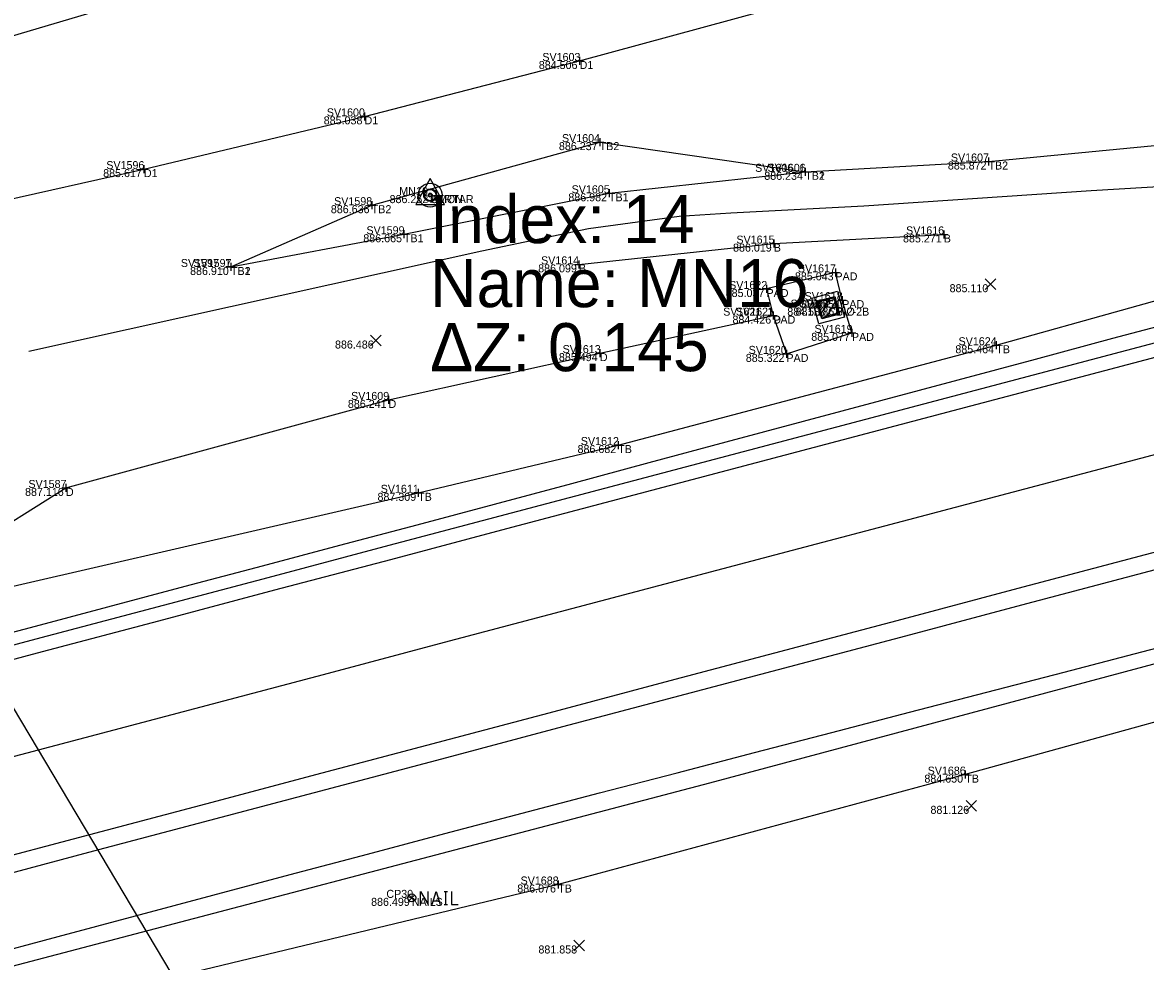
# Model space of a CAD drawing. Extents: x 2125299 to 2129212, y 713100 to 714300.
# Drawn here: x 2127665 to 2127805.3, y 713771.1 to 713888.4 of the extents above; entities that cross this region are included whole.
import ezdxf

# ---------------------------------------------------------------- set-up
doc = ezdxf.new("R2010")
doc.units = 0
for name, color, linetype in [('_CIVIL_CONSTRUCTION', 7, 'Continuous'), ('DR_X_Ditch', 7, 'Continuous'), ('DR_X_Storm_Sewer', 7, 'Continuous'), ('PV_X_EOP', 7, 'Continuous'), ('PV_X_Shoulder_Rumble_Strip', 7, 'Continuous'), ('RD_X_Concrete_Pad', 7, 'Continuous'), ('RS_Raster1', 7, 'Continuous'), ('RW_P_Esmt_TMP', 7, 'Continuous'), ('RW_X_CL', 7, 'Continuous'), ('RW_X_CL_100_Bearings', 7, 'Continuous'), ('RW_X_CL_100_Cardinal_Points', 7, 'Continuous'), ('RW_X_Esmt_CH', 7, 'Continuous'), ('RW_X_Fee_WL', 7, 'Continuous'), ('SC_Scratch1', 7, 'Continuous'), ('SC_Scratch2', 7, 'Continuous'), ('SV_P_Aerial_Targets', 7, 'Continuous'), ('SV_X_Break_Lines', 7, 'Continuous'), ('SV_X_Mon_Cells_Found', 7, 'Continuous'), ('SV_X_Text_Comment', 7, 'Continuous'), ('SV_X_Text_Elevation', 7, 'Continuous'), ('SV_X_Text_Name', 7, 'Continuous'), ('SV_X_Top_of_Bank', 7, 'Continuous')]:
    doc.layers.add(name, color=color, linetype=linetype)

msp = doc.modelspace()

# ---------------------------------------------------------------- linework, layer by layer
at = {"layer": '_CIVIL_CONSTRUCTION'}
msp.add_line((2127715.95, 713866.84), (2127715.95, 713866.84), dxfattribs=at)
msp.add_lwpolyline([(2127659.73, 713795.61), (2127674.23, 713799.44), (2127688.74, 713803.28), (2127703.24, 713807.12), (2127717.74, 713810.96), (2127732.24, 713814.8), (2127746.74, 713818.64), (2127761.24, 713822.47), (2127775.74, 713826.31), (2127790.24, 713830.15), (2127804.74, 713833.98), (2127819.24, 713837.82), (2127833.74, 713841.66), (2127848.24, 713845.49), (2127862.75, 713849.33), (2127877.25, 713853.16), (2127891.75, 713857), (2127906.25, 713860.83), (2127920.75, 713864.67)], dxfattribs=at)
msp.add_circle((2127715.95, 713866.84), 0.25, dxfattribs=at)
at = {"layer": 'DR_X_Ditch'}
for points in [[(2127104.46, 713722.2), (2127161.17, 713739.36), (2127224.94, 713755.07), (2127279.95, 713770.84), (2127341.71, 713787.57), (2127396.23, 713800.84), (2127459.54, 713814.71), (2127515.88, 713829.56), (2127633.42, 713858.63), (2127660.82, 713865.77), (2127680.17, 713870.09), (2127707.74, 713876.68), (2127734.62, 713883.6), (2127780.13, 713896.01), (2127811.25, 713900.24), (2127854.87, 713906.28), (2127890.1, 713912.55), (2127900.96, 713914.65)], [(2127114.72, 713683.53), (2127174.42, 713700.51), (2127233.48, 713715.29), (2127290.34, 713734.33), (2127349.42, 713751.95), (2127405.14, 713769), (2127465.12, 713782.63), (2127526.43, 713796.66), (2127583.18, 713810.08), (2127641.36, 713825.21), (2127649.66, 713823.32), (2127658.57, 713822.87), (2127670.43, 713830.25), (2127710.74, 713841.25), (2127737.15, 713847.1), (2127758.82, 713851.78)]]:
    msp.add_lwpolyline(points, dxfattribs=at)
at = {"layer": 'DR_X_Storm_Sewer'}
msp.add_line((2127551.46, 713991.15), (2127754.53, 713650.69), dxfattribs=at)
at = {"layer": 'PV_X_EOP'}
for points in [[(2127656.31, 713810.27), (2127665.98, 713812.83), (2127675.65, 713815.39), (2127685.31, 713817.96), (2127694.98, 713820.52), (2127704.64, 713823.08), (2127714.31, 713825.65), (2127723.97, 713828.22), (2127733.63, 713830.82), (2127743.29, 713833.42), (2127752.94, 713836.01), (2127762.6, 713838.6), (2127772.26, 713841.19), (2127781.92, 713843.77), (2127791.58, 713846.36), (2127801.24, 713848.95), (2127810.91, 713851.5)], [(2127659.79, 713771.64), (2127669.45, 713774.21), (2127679.11, 713776.79), (2127688.78, 713779.36), (2127698.44, 713781.93), (2127708.1, 713784.51), (2127717.77, 713787.08), (2127727.44, 713789.63), (2127737.11, 713792.15), (2127746.79, 713794.66), (2127756.47, 713797.18), (2127766.15, 713799.7), (2127775.83, 713802.22), (2127785.5, 713804.73), (2127795.18, 713807.25), (2127804.86, 713809.77), (2127814.54, 713812.29)]]:
    msp.add_lwpolyline(points, dxfattribs=at)
at = {"layer": 'PV_X_Shoulder_Rumble_Strip'}
for points in [[(2127652.21, 713807.54), (2127666.7, 713811.39), (2127681.2, 713815.24), (2127695.69, 713819.08), (2127710.19, 713822.92), (2127724.69, 713826.75), (2127739.19, 713830.59), (2127753.68, 713834.42), (2127768.18, 713838.25), (2127782.68, 713842.09), (2127797.18, 713845.92), (2127811.68, 713849.75), (2127826.18, 713853.59), (2127840.68, 713857.42), (2127855.17, 713861.25), (2127869.67, 713865.09), (2127884.17, 713868.92), (2127898.67, 713872.75), (2127913.17, 713876.59), (2127927.67, 713880.42), (2127936.81, 713882.83)], [(2127659.41, 713781.04), (2127673.9, 713784.89), (2127688.4, 713788.73), (2127702.89, 713792.57), (2127717.39, 713796.42), (2127731.89, 713800.26), (2127746.38, 713804.1), (2127760.88, 713807.95), (2127775.37, 713811.79), (2127789.87, 713815.63), (2127804.37, 713819.48), (2127818.86, 713823.32), (2127833.36, 713827.16), (2127847.85, 713831.01), (2127862.35, 713834.85), (2127876.84, 713838.69), (2127891.34, 713842.54), (2127905.84, 713846.37), (2127920.34, 713850.2), (2127928.07, 713852.23)]]:
    msp.add_lwpolyline(points, dxfattribs=at)
at = {"layer": 'RD_X_Concrete_Pad'}
msp.add_lwpolyline([(2127757.97, 713855.11), (2127758.82, 713851.78), (2127760.46, 713847), (2127768.65, 713849.63), (2127767.43, 713853.72), (2127766.58, 713857.19)], close=True, dxfattribs=at)
at = {"layer": 'RS_Raster1'}
msp.add_lwpolyline([(2127665.8, 713847.33), (2127722.38, 713859.86), (2127735.74, 713862.67), (2127747.07, 713864.19), (2127753.51, 713864.63), (2127770.12, 713865.48), (2127798.56, 713867.4), (2127815.33, 713868.4), (2127824.46, 713869.11), (2127836.01, 713870.37), (2127852.68, 713872.56), (2127871.22, 713875.21), (2127888.51, 713877.86), (2127910.9, 713881.86), (2127918.62, 713883.3), (2127925.53, 713884.74), (2127939.36, 713888.03)], dxfattribs=at)
at = {"layer": 'RW_X_CL'}
for radius in [1.5, 0.8]:
    msp.add_circle((2127715.95, 713866.84), radius, dxfattribs=at)
at = {"layer": 'RW_X_CL_100_Bearings'}
for p, q in [((2127765.24, 713854.39), (2127765.24, 713854.39)), ((2127765.42, 713853.75), (2127765.42, 713853.75)), ((2127764.71, 713852.52), (2127764.71, 713852.52)), ((2127765.68, 713852.78), (2127765.68, 713852.78)), ((2127765.68, 713852.78), (2127765.68, 713852.78)), ((2127765.68, 713852.78), (2127765.68, 713852.78)), ((2127766.64, 713853.04), (2127766.64, 713853.04)), ((2127765.94, 713851.82), (2127765.94, 713851.82)), ((2127766.11, 713851.17), (2127766.11, 713851.17))]:
    msp.add_line(p, q, dxfattribs=at)
at = {"layer": 'RW_X_CL_100_Cardinal_Points'}
for p, q in [((2127766.2, 713852.79), (2127767.2, 713852.79)), ((2127766.7, 713853.29), (2127766.7, 713852.29)), ((2127766.7, 713852.79), (2127766.7, 713852.79))]:
    msp.add_line(p, q, dxfattribs=at)
at = {"layer": 'SC_Scratch1'}
msp.add_lwpolyline([(2127133.38, 713627.43), (2127166.26, 713637.18), (2127280.77, 713668.85), (2127395.3, 713699.47), (2127509.42, 713729.99), (2127750.89, 713793.4), (2127929.41, 713841.22)], dxfattribs=at)
at = {"layer": 'SC_Scratch2'}
for points in [[(2127653.02, 713805.95), (2127667.52, 713809.8), (2127682.02, 713813.65), (2127696.52, 713817.5), (2127711.02, 713821.33), (2127725.52, 713825.17), (2127740.02, 713829), (2127754.52, 713832.83), (2127769.02, 713836.67), (2127783.52, 713840.5), (2127798.03, 713844.34), (2127812.53, 713848.17), (2127827.03, 713852.01), (2127841.53, 713855.84), (2127856.03, 713859.67), (2127870.54, 713863.51), (2127885.04, 713867.34), (2127899.54, 713871.18), (2127914.04, 713875.01), (2127928.54, 713878.84), (2127943.04, 713882.68), (2127957.55, 713886.51), (2127972.05, 713890.34)], [(2127658.93, 713783.11), (2127673.43, 713786.96), (2127687.93, 713790.8), (2127702.43, 713794.64), (2127716.93, 713798.49), (2127731.43, 713802.33), (2127745.92, 713806.18), (2127760.42, 713810.02), (2127774.92, 713813.87), (2127789.42, 713817.71), (2127803.92, 713821.55), (2127818.42, 713825.4), (2127832.92, 713829.24), (2127847.42, 713833.09), (2127861.92, 713836.93), (2127876.42, 713840.78), (2127890.92, 713844.62), (2127905.42, 713848.46), (2127919.92, 713852.28)]]:
    msp.add_lwpolyline(points, dxfattribs=at)
at = {"layer": 'SV_P_Aerial_Targets'}
msp.add_line((2127715.95, 713866.84), (2127715.95, 713866.84), dxfattribs=at)
msp.add_lwpolyline([(2127714.15, 713865.68), (2127717.75, 713865.68), (2127715.95, 713868.9)], close=True, dxfattribs=at)
for radius in [0.7, 0.16]:
    msp.add_circle((2127715.95, 713866.84), radius, dxfattribs=at)
at = {"layer": 'SV_X_Break_Lines'}
msp.add_lwpolyline([(2127734.52, 713858.19), (2127758.88, 713860.78), (2127780.12, 713861.93)], dxfattribs=at)
at = {"layer": 'SV_X_Mon_Cells_Found'}
for p, q in [((2127734.12, 713883.6), (2127735.12, 713883.6)), ((2127734.62, 713884.1), (2127734.62, 713883.1)), ((2127734.62, 713883.6), (2127734.62, 713883.6)), ((2127707.24, 713876.68), (2127708.24, 713876.68)), ((2127707.74, 713877.18), (2127707.74, 713876.18)), ((2127707.74, 713876.68), (2127707.74, 713876.68)), ((2127736.63, 713873.46), (2127737.63, 713873.46)), ((2127737.13, 713873.96), (2127737.13, 713872.96)), ((2127737.13, 713873.46), (2127737.13, 713873.46)), ((2127680.17, 713870.59), (2127680.17, 713869.59)), ((2127785.21, 713871.04), (2127786.21, 713871.04)), ((2127785.71, 713871.54), (2127785.71, 713870.54)), ((2127785.71, 713871.04), (2127785.71, 713871.04)), ((2127679.67, 713870.09), (2127680.67, 713870.09)), ((2127680.17, 713870.09), (2127680.17, 713870.09)), ((2127762.31, 713869.75), (2127763.31, 713869.75)), ((2127762.31, 713869.75), (2127763.31, 713869.75)), ((2127762.81, 713870.25), (2127762.81, 713869.25)), ((2127762.81, 713870.25), (2127762.81, 713869.25)), ((2127762.81, 713869.75), (2127762.81, 713869.75)), ((2127762.81, 713869.75), (2127762.81, 713869.75)), ((2127737.79, 713867.07), (2127738.79, 713867.07)), ((2127738.29, 713867.57), (2127738.29, 713866.57)), ((2127738.29, 713867.07), (2127738.29, 713867.07)), ((2127708.14, 713865.58), (2127709.14, 713865.58)), ((2127708.64, 713866.08), (2127708.64, 713865.08)), ((2127708.64, 713865.58), (2127708.64, 713865.58)), ((2127712.66, 713862.45), (2127712.66, 713861.45)), ((2127780.12, 713862.43), (2127780.12, 713861.43)), ((2127712.16, 713861.95), (2127713.16, 713861.95)), ((2127712.66, 713861.95), (2127712.66, 713861.95)), ((2127758.38, 713860.78), (2127759.38, 713860.78)), ((2127758.88, 713861.28), (2127758.88, 713860.28)), ((2127758.88, 713860.78), (2127758.88, 713860.78)), ((2127779.62, 713861.93), (2127780.62, 713861.93)), ((2127780.12, 713861.93), (2127780.12, 713861.93)), ((2127691.05, 713858.36), (2127691.05, 713857.36)), ((2127691.05, 713858.36), (2127691.05, 713857.36)), ((2127734.02, 713858.19), (2127735.02, 713858.19)), ((2127734.52, 713858.69), (2127734.52, 713857.69)), ((2127734.52, 713858.19), (2127734.52, 713858.19)), ((2127690.55, 713857.86), (2127691.55, 713857.86)), ((2127690.55, 713857.86), (2127691.55, 713857.86)), ((2127691.05, 713857.86), (2127691.05, 713857.86)), ((2127691.05, 713857.86), (2127691.05, 713857.86)), ((2127766.08, 713857.19), (2127767.08, 713857.19)), ((2127766.58, 713857.69), (2127766.58, 713856.69)), ((2127766.58, 713857.19), (2127766.58, 713857.19)), ((2127757.97, 713855.61), (2127757.97, 713854.61)), ((2127757.47, 713855.11), (2127758.47, 713855.11)), ((2127757.97, 713855.11), (2127757.97, 713855.11)), ((2127767.43, 713854.22), (2127767.43, 713853.22)), ((2127766.93, 713853.72), (2127767.93, 713853.72)), ((2127767.43, 713853.72), (2127767.43, 713853.72)), ((2127758.32, 713851.78), (2127759.32, 713851.78)), ((2127758.32, 713851.78), (2127759.32, 713851.78)), ((2127758.82, 713852.28), (2127758.82, 713851.28)), ((2127758.82, 713852.28), (2127758.82, 713851.28)), ((2127758.82, 713851.78), (2127758.82, 713851.78)), ((2127758.82, 713851.78), (2127758.82, 713851.78)), ((2127768.15, 713849.63), (2127769.15, 713849.63)), ((2127768.65, 713850.13), (2127768.65, 713849.13)), ((2127768.65, 713849.63), (2127768.65, 713849.63)), ((2127786.69, 713848.58), (2127786.69, 713847.58)), ((2127736.65, 713847.1), (2127737.65, 713847.1)), ((2127737.15, 713847.6), (2127737.15, 713846.6)), ((2127737.15, 713847.1), (2127737.15, 713847.1)), ((2127759.96, 713847), (2127760.96, 713847)), ((2127760.46, 713847.5), (2127760.46, 713846.5)), ((2127760.46, 713847), (2127760.46, 713847)), ((2127786.19, 713848.08), (2127787.19, 713848.08)), ((2127786.69, 713848.08), (2127786.69, 713848.08)), ((2127710.24, 713841.25), (2127711.24, 713841.25)), ((2127710.74, 713841.75), (2127710.74, 713840.75)), ((2127710.74, 713841.25), (2127710.74, 713841.25)), ((2127738.94, 713835.61), (2127739.94, 713835.61)), ((2127739.44, 713836.11), (2127739.44, 713835.11)), ((2127739.44, 713835.61), (2127739.44, 713835.61)), ((2127669.93, 713830.25), (2127670.93, 713830.25)), ((2127670.43, 713830.75), (2127670.43, 713829.75)), ((2127670.43, 713830.25), (2127670.43, 713830.25)), ((2127714.44, 713830.14), (2127714.44, 713829.14)), ((2127713.94, 713829.64), (2127714.94, 713829.64)), ((2127714.44, 713829.64), (2127714.44, 713829.64)), ((2127782.81, 713794.93), (2127782.81, 713793.93)), ((2127782.31, 713794.43), (2127783.31, 713794.43)), ((2127782.81, 713794.43), (2127782.81, 713794.43)), ((2127731.94, 713781.2), (2127731.94, 713780.2)), ((2127731.44, 713780.7), (2127732.44, 713780.7)), ((2127731.94, 713780.7), (2127731.94, 713780.7))]:
    msp.add_line(p, q, dxfattribs=at)
at = {"layer": 'SV_X_Text_Comment'}
for p, q in [((2127764.44, 713852.98), (2127764.88, 713853.75)), ((2127764.73, 713851.89), (2127765.97, 713854.05)), ((2127765.45, 713851.53), (2127766.64, 713853.61)), ((2127766.54, 713851.83), (2127766.94, 713852.52))]:
    msp.add_line(p, q, dxfattribs=at)
for points in [[(2127763.64, 713853.96), (2127766.85, 713854.83), (2127767.72, 713851.61), (2127764.5, 713850.74)], [(2127764.27, 713853.59), (2127766.49, 713854.19), (2127767.08, 713851.97), (2127764.87, 713851.38)], [(2127764.45, 713853.49), (2127766.38, 713854.01), (2127766.9, 713852.08), (2127764.97, 713851.56)]]:
    msp.add_lwpolyline(points, close=True, dxfattribs=at)
at = {"layer": 'SV_X_Text_Elevation'}
for p, q in [((2127785.3, 713855.04), (2127786.63, 713856.38)), ((2127785.3, 713856.38), (2127786.63, 713855.04)), ((2127708.49, 713848), (2127709.82, 713849.34)), ((2127708.49, 713849.34), (2127709.82, 713848)), ((2127782.9, 713789.86), (2127784.23, 713791.2)), ((2127782.9, 713791.2), (2127784.23, 713789.86)), ((2127733.91, 713772.41), (2127735.24, 713773.75)), ((2127733.91, 713773.75), (2127735.24, 713772.41))]:
    msp.add_line(p, q, dxfattribs=at)
at = {"layer": 'SV_X_Text_Name'}
for p, q in [((2127713.29, 713779.38), (2127714, 713778.68)), ((2127713.29, 713778.68), (2127714, 713779.38))]:
    msp.add_line(p, q, dxfattribs=at)
for points in [[(2127714.74, 713778.22), (2127714.74, 713779.82), (2127715.68, 713778.22), (2127715.68, 713779.82)], [(2127716.19, 713778.22), (2127716.69, 713779.82), (2127717.18, 713778.22)], [(2127717.69, 713779.82), (2127718.09, 713779.82)], [(2127717.89, 713778.22), (2127717.89, 713779.82)], [(2127718.59, 713779.82), (2127718.59, 713778.22), (2127719.46, 713778.22)], [(2127717.06, 713778.6), (2127716.31, 713778.6)], [(2127717.69, 713778.22), (2127718.09, 713778.22)]]:
    msp.add_lwpolyline(points, dxfattribs=at)
msp.add_circle((2127713.65, 713779.03), 0.5, dxfattribs=at)
at = {"layer": 'SV_X_Top_of_Bank'}
for points in [[(2127101.4, 713732.92), (2127157.86, 713749.53), (2127222.47, 713767.6), (2127276.61, 713783.01), (2127338.05, 713802.99), (2127391.69, 713816.17), (2127455.85, 713833.15), (2127455.8, 713833.25), (2127510.11, 713848.18), (2127573.33, 713861.42), (2127627.49, 713877.76), (2127656.95, 713884.76), (2127703.68, 713898.62), (2127726.61, 713904.03), (2127772.75, 713915.63), (2127805.28, 713925.94), (2127847.55, 713937.37), (2127886.63, 713945.55), (2127933.44, 713957.72), (2127971.8, 713964.93)], [(2127691.05, 713857.86), (2127708.64, 713865.58), (2127737.13, 713873.46), (2127762.81, 713869.75), (2127785.71, 713871.04), (2127815.54, 713873.93), (2127860.68, 713880.21), (2127901.34, 713884.74), (2127930.61, 713889.81), (2127938.55, 713892.74), (2127941.1, 713904.01), (2127946.04, 713922.91), (2127948.74, 713934.84), (2127960.18, 713949.89), (2127971.8, 713964.93)], [(2127118.3, 713671.13), (2127177.41, 713689.33), (2127235.14, 713704.98), (2127293.81, 713721.23), (2127351.9, 713736.5), (2127410.59, 713750.81), (2127468.4, 713765.95), (2127530.81, 713781.83), (2127585.7, 713797.67), (2127644.65, 713813.57), (2127714.44, 713829.64), (2127739.44, 713835.61), (2127786.69, 713848.08), (2127820.06, 713857.41), (2127851.23, 713864.33), (2127885.98, 713873.89), (2127912.04, 713881.53)], [(2127691.05, 713857.86), (2127712.66, 713861.95), (2127738.29, 713867.07), (2127762.81, 713869.75)], [(2127920.85, 713834.18), (2127873.9, 713818.39), (2127828.31, 713807.04), (2127782.81, 713794.43), (2127731.94, 713780.7), (2127685.41, 713769.5), (2127638.8, 713755.97), (2127588.05, 713743.29)]]:
    msp.add_lwpolyline(points, dxfattribs=at)

# ---------------------------------------------------------------- texts
at = {"layer": '_CIVIL_CONSTRUCTION'}
for s, p in [('Index: 14', (2127715.95, 713860.84)), ('Name: MN16', (2127715.95, 713852.84)), ('ΔZ: 0.145', (2127715.95, 713844.84))]:
    msp.add_text(s, height=6, dxfattribs=at).set_placement(p)
at = {"layer": 'RW_P_Esmt_TMP'}
for s, p in [('D1', (2127734.62, 713882.6)), ('D1', (2127707.74, 713875.68)), ('TB2', (2127737.13, 713872.46)), ('TB2', (2127785.71, 713870.04)), ('D1', (2127680.17, 713869.09)), ('TB2', (2127762.81, 713868.75)), ('TB1', (2127762.81, 713868.75)), ('AERTAR', (2127715.95, 713865.84)), ('CMON', (2127715.95, 713865.84)), ('TB1', (2127738.29, 713866.07)), ('TB2', (2127708.64, 713864.58)), ('TB1', (2127712.66, 713860.95)), ('B', (2127758.88, 713859.78)), ('B', (2127780.12, 713860.93)), ('B', (2127734.52, 713857.19)), ('TB2', (2127691.05, 713856.86)), ('TB1', (2127691.05, 713856.86)), ('PAD', (2127766.58, 713856.19)), ('PAD', (2127757.97, 713854.11)), ('CB-2-2B', (2127765.68, 713851.78)), ('PIO', (2127766.7, 713851.79)), ('PAD', (2127767.43, 713852.72)), ('D', (2127758.82, 713850.78)), ('PAD', (2127758.82, 713850.78)), ('PAD', (2127768.65, 713848.63)), ('D', (2127737.15, 713846.1)), ('PAD', (2127760.46, 713846)), ('TB', (2127786.69, 713847.08)), ('D', (2127710.74, 713840.25)), ('TB', (2127739.44, 713834.61)), ('D', (2127670.43, 713829.25)), ('TB', (2127714.44, 713828.64)), ('TB', (2127782.81, 713793.43)), ('TB', (2127731.94, 713779.7)), ('NAILS', (2127713.65, 713778.03))]:
    msp.add_text(s, height=1, dxfattribs=at).set_placement(p)
at = {"layer": 'RW_X_Esmt_CH'}
for s, p in [('SV1603', (2127729.96, 713883.6)), ('SV1600', (2127703.03, 713876.68)), ('SV1604', (2127732.41, 713873.46)), ('SV1607', (2127781.01, 713871.04)), ('SV1596', (2127675.47, 713870.09)), ('SV1606_1', (2127756.55, 713869.75)), ('SV1606', (2127758.11, 713869.75)), ('MN16', (2127712.08, 713866.84)), ('MN16', (2127712.08, 713866.84)), ('SV1605', (2127733.62, 713867.07)), ('SV1598', (2127703.94, 713865.58)), ('SV1599', (2127707.98, 713861.95)), ('SV1616', (2127775.41, 713861.93)), ('SV1615', (2127754.21, 713860.78)), ('SV1597_1', (2127684.79, 713857.86)), ('SV1597', (2127686.36, 713857.86)), ('SV1614', (2127729.8, 713858.19)), ('SV1617', (2127761.89, 713857.19)), ('SV1622', (2127753.3, 713855.11)), ('SV1608', (2127760.98, 713852.78)), ('SV1623', (2127762.04, 713852.79)), ('SV1618', (2127762.73, 713853.72)), ('SV1621_1', (2127752.56, 713851.78)), ('SV1621', (2127754.15, 713851.78)), ('SV1619', (2127763.97, 713849.63)), ('SV1613', (2127732.49, 713847.1)), ('SV1624', (2127781.97, 713848.08)), ('SV1620', (2127755.74, 713847)), ('SV1609', (2127706.06, 713841.25)), ('SV1612', (2127734.77, 713835.61)), ('SV1587', (2127665.74, 713830.25)), ('SV1611', (2127709.76, 713829.64)), ('SV1686', (2127778.11, 713794.43)), ('SV1688', (2127727.24, 713780.7)), ('CP30', (2127710.47, 713779.03))]:
    msp.add_text(s, height=1, dxfattribs=at).set_placement(p)
at = {"layer": 'RW_X_Fee_WL'}
for s, p in [('884.506', (2127729.52, 713882.6)), ('885.038', (2127702.64, 713875.68)), ('886.237', (2127732.03, 713872.46)), ('885.872', (2127780.63, 713870.04)), ('885.617', (2127675.08, 713869.09)), ('886.234', (2127757.69, 713868.75)), ('886.234', (2127757.69, 713868.75)), ('886.252', (2127710.87, 713865.84)), ('886.252', (2127710.87, 713865.84)), ('886.982', (2127733.21, 713866.07)), ('886.636', (2127703.53, 713864.58)), ('886.665', (2127707.59, 713860.95)), ('886.019', (2127753.79, 713859.78)), ('885.271', (2127775.03, 713860.93)), ('886.099', (2127729.44, 713857.19)), ('886.910', (2127685.94, 713856.86)), ('886.910', (2127685.94, 713856.86)), ('885.043', (2127761.52, 713856.19)), ('885.037', (2127752.87, 713854.11)), ('885.110', (2127780.85, 713854.71)), ('884.754', (2127762.31, 713852.72)), ('884.580', (2127760.57, 713851.78)), ('881.186', (2127761.6, 713851.79)), ('884.426', (2127753.72, 713850.78)), ('884.426', (2127753.72, 713850.78)), ('885.077', (2127763.56, 713848.63)), ('886.486', (2127704.05, 713847.67)), ('885.494', (2127732.03, 713846.1)), ('885.322', (2127755.38, 713846)), ('885.464', (2127781.57, 713847.08)), ('886.241', (2127705.66, 713840.25)), ('886.682', (2127734.36, 713834.61)), ('887.116', (2127665.32, 713829.25)), ('887.309', (2127709.36, 713828.64)), ('884.650', (2127777.7, 713793.43)), ('881.126', (2127778.46, 713789.53)), ('886.076', (2127726.83, 713779.7)), ('886.499', (2127708.56, 713778.03)), ('881.858', (2127729.47, 713772.08))]:
    msp.add_text(s, height=1, dxfattribs=at).set_placement(p)

doc.saveas('drawing.dxf')
